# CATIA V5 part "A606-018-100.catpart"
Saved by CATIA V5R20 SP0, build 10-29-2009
Part number: A606-018-100
Source: Unknown
Property "ARTICLENO": "A606-018-100"
Property "BOMINFO": "A606-018-100"
Property "CODE": "A606-018-100"
Property "HOLES": "2"
Property "L": "100.000"
Property "L1": "25.000"
Property "L2": "50.000"
Property "LINA": "A606-018-100"
Property "NB": "A606-018-100"
Property "NBSYN": "$CODE."
Property "NN": "A606"
Property "NT": "Wear Plates, self-lubricating"
Property "SCREW": "2xM6"
Property "SUPPLIER": "CF"
Property "W": "18.000"
Bounding box of the stored display mesh (mm): x -9 to 9, y -5 to 5, z -50 to 50
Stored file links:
  C:\Users\Utente\Desktop\3D files A606\A606-018-100.catpart
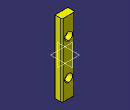
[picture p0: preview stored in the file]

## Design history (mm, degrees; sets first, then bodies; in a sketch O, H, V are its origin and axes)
Body1 "Geometry.1" (main body)
  Solid1 "A606-018-100.catpart": solid without history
